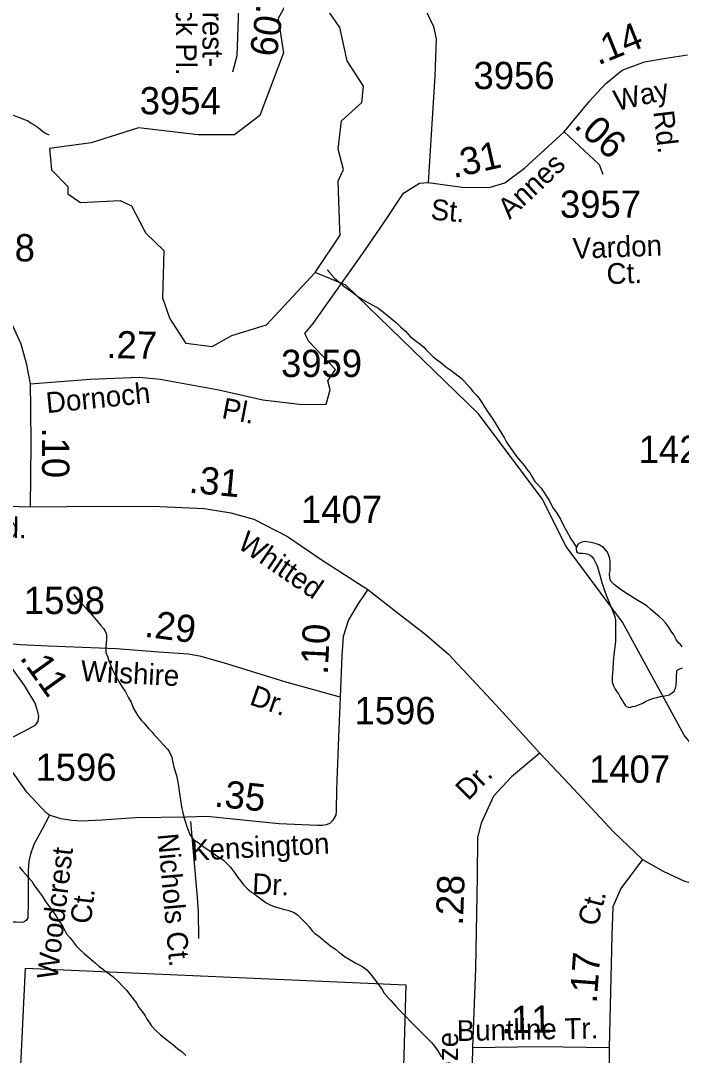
# Model space of a CAD drawing. Extents: x 2001466 to 2224147, y 644118 to 847247.
# Drawn here: x 2068297 to 2071329, y 678756 to 683500 of the extents above; entities that cross this region are included whole.
import ezdxf

# ---------------------------------------------------------------- set-up
doc = ezdxf.new("R2010")
doc.units = 0
for name, color, linetype in [('Exist Boundary Political City Limit New', 7, 'Continuous'), ('Exist Hydrographic Misc Water Feature', 7, 'Continuous'), ('Exist Road Non-System Type 51', 7, 'Continuous'), ('Exist Road Non-System Type 51 Label', 7, 'Continuous'), ('Exist Road Secondary Mileage Hundredths English Label', 7, 'Continuous'), ('Exist Road Secondary Type 51 Attributed', 7, 'Continuous'), ('Exist Road Secondary Type 51 Label', 7, 'Continuous'), ('Exist Road Secondary Type 51 Number Label', 7, 'Continuous'), ('Map Preparation Boundary City Limit Buffer Line', 7, 'Continuous')]:
    doc.layers.add(name, color=color, linetype=linetype)

msp = doc.modelspace()

# ---------------------------------------------------------------- linework, layer by layer
at = {"layer": 'Exist Boundary Political City Limit New'}
msp.add_lwpolyline([(2070065, 679078.5), (2069979.9, 676124.6), (2067235.2, 676200.2), (2067007.2, 676474), (2066845.5, 676712.3), (2066718.2, 677001.4), (2066684.1, 677222.8), (2066689.2, 677418.8), (2066711.6, 677519), (2066797.6, 677765.7), (2066838.9, 678102.1), (2066857.5, 678775), (2068293.8, 678644.4), (2068319.2, 679155.1), (2070065, 679078.5)], dxfattribs=at)
at = {"layer": 'Exist Hydrographic Misc Water Feature'}
for p, q in [((2068863.6, 682539.1), (2068870.7, 682525.4)), ((2069647.7, 682345.6), (2069762.7, 682517.1)), ((2069762.7, 682517.1), (2069761.7, 682540.8))]:
    msp.add_line(p, q, dxfattribs=at)
for points in [[(2069761.7, 682540.8), (2069753.7, 682766.6), (2069778.7, 682818.6), (2069753.7, 682911), (2069769.7, 683041.9), (2069861.8, 683125.4), (2069869.8, 683200.6), (2069794.7, 683317), (2069760.7, 683468.6), (2069677.6, 683591.7), (2069510.7, 683568.8), (2069477.7, 683510.4), (2069502.7, 683352.4)], [(2069502.7, 683352.4), (2069394.6, 683065.9), (2069278.6, 682976.5), (2069111.7, 682976.6), (2068836.7, 683008.4), (2068620.6, 682940.6), (2068428.6, 682915), (2068437.7, 682816.4), (2068512.7, 682739.4), (2068512.7, 682706.6), (2068570.7, 682666.1), (2068753.7, 682675.4), (2068804.7, 682651.5), (2068863.6, 682539.1)], [(2068024.9, 683277.7), (2068042.9, 683240.2), (2068058.7, 683217.9), (2068078.6, 683194.2), (2068096.9, 683176), (2068110.8, 683168.2), (2068149, 683144.2), (2068173.2, 683128.3), (2068195.1, 683112.4), (2068210.9, 683100.3), (2068235.1, 683082.4), (2068257, 683068.6), (2068291.3, 683056.5), (2068317.1, 683046.5), (2068327.1, 683042.5), (2068345, 683030.5), (2068359.1, 683022.7), (2068377.4, 683010.5), (2068385.4, 683002.4), (2068397.5, 682992.6), (2068407.5, 682986.6), (2068419.2, 682980.7), (2068427, 682976.7)], [(2069647.7, 682345.6), (2069423.6, 682104.1), (2069264.6, 682054.8), (2069173.6, 682004.2), (2069056.7, 682019.7), (2068981.7, 682136.1), (2068948.7, 682228.5), (2068955.6, 682444.9), (2068870.7, 682525.4)], [(2069703.7, 682357.7), (2069713.9, 682345.6), (2069737.7, 682319.7), (2069757.6, 682302.1), (2069775.8, 682285.9), (2069810.1, 682262.1), (2069828.1, 682248), (2069843.9, 682236.3), (2069868.1, 682220), (2069889.8, 682208.2), (2069916.1, 682194.1), (2069937.8, 682182.3), (2069962, 682164.4), (2069980.3, 682148.3), (2070019.9, 682116.3), (2070039.9, 682096.6), (2070062.3, 682076.6), (2070084, 682052.6), (2070111.9, 682030.6), (2070128.1, 682018.8), (2070146.4, 682002.6), (2070156.2, 681992.6), (2070190, 681958.7), (2070204.2, 681948.8), (2070224.5, 681932.8), (2070248.3, 681913), (2070266.3, 681900.9), (2070290.5, 681883), (2070318.2, 681861), (2070332.6, 681847.1), (2070354.5, 681821), (2070372.5, 681799.2), (2070394.9, 681777.2), (2070412.7, 681749.3), (2070428.7, 681725.4), (2070442.9, 681703.4), (2070460.7, 681677.1), (2070474.9, 681655.5), (2070492.7, 681625.3), (2070504.8, 681605.6), (2070516.7, 681585.5), (2070526.9, 681567.8), (2070542.9, 681543.4), (2070558.7, 681521.6), (2070572.9, 681501.6), (2070590.9, 681479.8), (2070609.2, 681459.5), (2070618.8, 681445.9), (2070633.2, 681427.5), (2070645.3, 681405.8), (2070657.2, 681387.8), (2070671.1, 681371.9), (2070685, 681356)], [(2072829.5, 678435.8), (2072653.5, 678511.5), (2072570.5, 678618.2), (2072377.5, 679019.1), (2072375, 679070.2), (2072367.6, 679129.4), (2072342, 679180.5), (2072292.9, 679275.5), (2072277.5, 679295.3), (2072268.7, 679305.2), (2072253.3, 679326.9), (2072130.2, 679713.7), (2072075.9, 679756.2), (2071543.6, 679974.4), (2071342.6, 680224.5), (2071058.6, 680742.1), (2070799.7, 681088.6), (2070690.6, 681307.3), (2070398.6, 681697.1), (2069789.6, 682287), (2069647.7, 682345.6)], [(2070685, 681356), (2070723.4, 681297.8), (2070737.3, 681269.8), (2070757.4, 681242), (2070773.6, 681214), (2070787.6, 681185.9), (2070801.7, 681160.3), (2070821.6, 681124), (2070831.7, 681108.2), (2070847.6, 681084.3)], [(2070847.6, 681084.3), (2070845.6, 681080.2), (2070847.6, 681066.1), (2070851.5, 681062.2), (2070859.7, 681058.1), (2070875.5, 681058.2), (2070889.7, 681056.5), (2070901.8, 681054.2), (2070911.8, 681048.3), (2070919.6, 681042.2), (2070927.8, 681030.4), (2070934, 681018.5), (2070939.9, 681006.3), (2070943.8, 680996.3), (2070949.6, 680974.4), (2070955.7, 680952.3), (2070963.7, 680924.3), (2070972.1, 680900.4), (2070983.8, 680866.6), (2070995.9, 680836.7), (2071008.4, 680806.5), (2071014.1, 680790.6), (2071018.5, 680780.6), (2071024.2, 680766.8), (2071026, 680752.7), (2071026.5, 680736.4), (2071026.2, 680720.6), (2071026, 680696.7), (2071026.2, 680674.7), (2071026.2, 680654.5), (2071018.7, 680590.7), (2071016.6, 680560.6), (2071014.8, 680524.4), (2071012.7, 680506.5), (2071010.7, 680488.6), (2071010.7, 680466.6), (2071017, 680450.7), (2071025, 680434.8), (2071032.8, 680422.7), (2071040.8, 680412.6), (2071047, 680400.7), (2071052.9, 680390.9), (2071058.9, 680380.7), (2071065, 680370.8), (2071070.9, 680361), (2071076.7, 680354.8), (2071084.9, 680352.8), (2071093.1, 680350.7), (2071105.2, 680355), (2071119.1, 680356.9), (2071132.9, 680362.9), (2071148.9, 680369.1), (2071164.9, 680378.8), (2071185, 680387.1), (2071202.8, 680392.9), (2071216.7, 680396.9), (2071232.7, 680401), (2071246.7, 680403.3), (2071259, 680405.1), (2071272.7, 680409.1), (2071282.8, 680415.3), (2071288.9, 680419.2), (2071297.1, 680427.3), (2071298.8, 680433.1)], [(2071332.4, 680629.2), (2071324.4, 680639.3), (2071316.2, 680647.1), (2071304.5, 680663), (2071294.2, 680683.3), (2071282.4, 680701.3), (2071270.3, 680720.9), (2071255.9, 680738.9), (2071242, 680754.8), (2071226, 680769), (2071212.2, 680780.8), (2071199.9, 680790.8), (2071188.4, 680800.7), (2071172, 680814.9), (2071160.1, 680822.8), (2071147.8, 680830.7), (2071130, 680840.7), (2071104.2, 680856.8), (2071080.2, 680872.7), (2071053.9, 680888.8), (2071035.9, 680902.5), (2071019.9, 680914.6), (2071005.9, 680930.6), (2071001.8, 680938.4), (2071000, 680948.4), (2070999.8, 680962.3), (2071002.1, 680980.6), (2071001.8, 680994.4), (2071002.1, 681010.6), (2071001.8, 681020.4), (2071000, 681034.5), (2070995.5, 681048.5), (2070989.7, 681062.4), (2070981.5, 681074.5), (2070971.7, 681084.6), (2070951.6, 681096.5), (2070934, 681102.5), (2070915.7, 681108.1), (2070895.8, 681110.3), (2070885.4, 681112.3), (2070871.6, 681108.3), (2070857.9, 681102.2), (2070853.8, 681098.4), (2070849.9, 681090.1), (2070847.6, 681084.3)], [(2068540.6, 680868.2), (2068560.9, 680842), (2068578.7, 680824.3), (2068602.9, 680798.3), (2068624.9, 680774.3), (2068642.7, 680752.1), (2068662.6, 680728.4), (2068676.6, 680712.5), (2068684.8, 680700.3), (2068689.1, 680690.3), (2068691.1, 680682.3), (2068690.7, 680670.2), (2068690.7, 680662.5), (2068688.9, 680646.1), (2068687, 680632.3), (2068686.8, 680618.5), (2068687, 680602.2), (2068695.2, 680584.4), (2068701.2, 680564.4), (2068709.4, 680546.5), (2068717, 680526.3), (2068729.3, 680502.6), (2068751.4, 680462.7), (2068761, 680446.6), (2068777.4, 680422.6), (2068791.4, 680394.5), (2068803.5, 680374.5), (2068813.5, 680348.6), (2068823.4, 680330.5), (2068833.6, 680312.7), (2068841.6, 680302.6), (2068849.8, 680292.8), (2068861.3, 680280.5), (2068883.9, 680254.8), (2068899.4, 680237), (2068909.9, 680224.9), (2068921.8, 680212.9), (2068938, 680194.7), (2068951.9, 680178.8), (2068969.8, 680159), (2068978, 680148.9), (2068989.9, 680123.2), (2068993.6, 680105.1), (2068999.9, 680077), (2069011.8, 680039.1), (2069018, 680008.9), (2069020.2, 679989.2), (2069024.1, 679967.1), (2069026.4, 679946.9), (2069030.3, 679925.2), (2069034.2, 679894.9), (2069042.2, 679861.3), (2069048.3, 679839.3), (2069062.7, 679795.3), (2069074.2, 679765.2), (2069088.7, 679747.2), (2069106.5, 679735.1), (2069132.6, 679715.4), (2069170.3, 679689.4), (2069190.6, 679675.4), (2069206.4, 679663.6), (2069226.5, 679651.6), (2069242.5, 679635.4), (2069258.7, 679619.6), (2069280.4, 679589.6), (2069292.7, 679571.5), (2069306.7, 679553.5), (2069320.8, 679535.6), (2069334.6, 679521.7), (2069356.7, 679503.7), (2069367.2, 679497.7), (2069387.1, 679481.7), (2069410.8, 679463.9), (2069427, 679453.8), (2069444.9, 679444.1), (2069464.8, 679435.9), (2069481.2, 679432.2), (2069500.9, 679425.9), (2069526.7, 679420), (2069551.1, 679410.2), (2069567.1, 679400), (2069576.9, 679390), (2069586.8, 679380.5), (2069606.9, 679360.4), (2069621.2, 679344.4), (2069635.2, 679326.5), (2069647.3, 679314.5), (2069665.3, 679302.4), (2069683, 679286.4), (2069689.3, 679280.5), (2069709.2, 679264.6), (2069720.9, 679256.7), (2069741.6, 679242.6), (2069757.4, 679228.5), (2069771.1, 679218.7), (2069783, 679208.7), (2069819.3, 679186.6), (2069835.5, 679178.9), (2069853.3, 679168.9), (2069867.3, 679160.7)], [(2071298.8, 680433.1), (2071302.9, 680439.4), (2071304.7, 680453.3), (2071306.8, 680475.3), (2071306.8, 680495.2), (2071308.8, 680513.1), (2071308.6, 680519.2), (2071312.5, 680523.1), (2071322.5, 680527.3), (2071334.6, 680533.1)], [(2068289.2, 679619.8), (2068306.6, 679600), (2068329.2, 679573.9), (2068347, 679553.8), (2068357.1, 679538), (2068378.8, 679508), (2068397.1, 679484.1), (2068407.1, 679466), (2068417.4, 679450.2), (2068438.9, 679422.2), (2068459.4, 679394.4), (2068471.5, 679372.3), (2068489.3, 679346.4), (2068499.4, 679328.3), (2068507.4, 679312.1), (2068523.6, 679294.2), (2068541.6, 679270.3), (2068551.5, 679258.3), (2068569.5, 679238.6), (2068587.6, 679222.4), (2068599.7, 679212.5), (2068619.3, 679196.5), (2068639.9, 679178.4), (2068655.8, 679164.6), (2068665.5, 679156.7), (2068691.9, 679136.4), (2068719.6, 679116.9), (2068745.9, 679092.6), (2068763.7, 679072.8), (2068783.8, 679052.8), (2068795.9, 679036.7), (2068817.6, 679008.7), (2068829.9, 678993.1), (2068837.9, 678976.8), (2068854.1, 678956.9), (2068868.1, 678936.9), (2068876.1, 678921.1), (2068886.1, 678907), (2068896.2, 678892.9), (2068915.9, 678871.3), (2068938.2, 678849.3), (2068960.1, 678833.4), (2068974.3, 678821.1), (2068994, 678807.1), (2069018.4, 678785.2), (2069038.3, 678771.2), (2069054.3, 678755.4)], [(2069867.3, 679160.7), (2069885.5, 679147), (2069903.4, 679126.9), (2069919.6, 679106.9), (2069939.5, 679080.8), (2069955.5, 679056.9), (2069965.5, 679041.1), (2069989.7, 679013.2), (2069995.7, 679007), (2070017.6, 678983), (2070035.4, 678963.2), (2070057.8, 678939.2), (2070093.9, 678903.3), (2070106, 678891.3), (2070139.8, 678857.4), (2070151.9, 678845.4), (2070171.8, 678825.3), (2070183.9, 678813.4), (2070196.2, 678797.3), (2070212, 678775.5), (2070228.2, 678747.5)]]:
    msp.add_lwpolyline(points, dxfattribs=at)
at = {"layer": 'Exist Road Non-System Type 51'}
for points in [[(2069698.8, 681741.8), (2069717.8, 681808.2), (2069706.7, 681849.2), (2069741.4, 681901.3), (2069618.4, 682029.2), (2069601, 682065.5), (2069638.9, 682111.3), (2069866.1, 682431.1), (2069963.9, 682573.2), (2070053.1, 682710.2), (2070126.5, 682756), (2070166.7, 682757.6)], [(2069075.3, 679827.7), (2069106.6, 679479.6), (2069111.3, 679414), (2069112.9, 679291.3)]]:
    msp.add_lwpolyline(points, dxfattribs=at)
at = {"layer": 'Exist Road Secondary Type 51 Attributed'}
for points in [[(2069295.3, 683730.5), (2069296.9, 683556), (2069288.2, 683338.5), (2069268.4, 683264.3)], [(2070053.5, 683655.1), (2070145, 683568.2), (2070190.8, 683473.9), (2070204.2, 683417), (2070197.9, 683245.3), (2070185.2, 683051.1), (2070166.7, 682757.6)], [(2070790.8, 682990.1), (2070909.1, 683132.2), (2070981.3, 683211.4), (2071057.8, 683273.7), (2071160.4, 683311.6), (2071257.5, 683328.2), (2071356.5, 683343.8)], [(2070166.7, 682757.6), (2070322.9, 682736.3), (2070447.6, 682735.1), (2070519.4, 682757.2), (2070609.3, 682823.5), (2070790.8, 682990.1)], [(2070790.8, 682990.1), (2070952.5, 682840.9), (2070968.3, 682796.7)], [(2067025.8, 682675.6), (2067145.1, 682631.1), (2067505.1, 682504.7), (2067888.5, 682374.1), (2068062.9, 682297.5), (2068140.2, 682242.2), (2068201.7, 682183.8), (2068258.6, 682103.2), (2068298, 682018), (2068321.7, 681929.9), (2068340.2, 681835)], [(2068340.2, 681835), (2068614.8, 681856.3), (2068842, 681865.8), (2068936.7, 681856.3), (2069206.5, 681807.4), (2069408.5, 681762.4), (2069588.4, 681740.3), (2069698.8, 681741.8)], [(2068340.2, 681835), (2068341.8, 681721.3), (2068343.4, 681557.1), (2068340.2, 681270.5)], [(2066812.8, 681282.8), (2066924.1, 681283.8), (2067271.7, 681279.7), (2067453, 681276.6), (2067836.8, 681285.5), (2068340.2, 681270.5)], [(2068340.2, 681270.5), (2068677.1, 681274), (2068935.9, 681272.5), (2069139.4, 681263), (2069260.9, 681244), (2069366.7, 681214), (2069521.3, 681134.3), (2069680.7, 681026.9), (2069890.6, 680891.9)], [(2069890.6, 680891.9), (2069846.4, 680829.9), (2069800.6, 680752.5), (2069776.9, 680676.8), (2069770.6, 680588.3), (2069762.7, 680397.3)], [(2069890.6, 680891.9), (2070045.2, 680771.1), (2070149.8, 680690.7), (2070259.8, 680595.6), (2070476.8, 680362.9), (2070678.7, 680141.1)], [(2068170.8, 680177.6), (2068267.6, 680219.7), (2068336, 680254.6), (2068366.7, 680271.4), (2068376.5, 680288.1), (2068379.3, 680309), (2068375.1, 680331.4), (2068363.4, 680370.8), (2068313.8, 680452.3), (2068255.9, 680532.6), (2068231.1, 680570.3), (2068218.1, 680602.2), (2068214.6, 680618.7), (2068216.9, 680632.9), (2068228.7, 680641.2), (2068248.7, 680642)], [(2069762.7, 680397.3), (2069508.7, 680469.1), (2069246.7, 680549.6), (2069125.4, 680585.2), (2069066.2, 680595.4), (2068930.7, 680604.8), (2068735.6, 680619.5), (2068423.7, 680631.7), (2068294.9, 680638.8), (2068248.7, 680642)], [(2069762.7, 680397.3), (2069754.8, 680214.9), (2069745.4, 679974.9), (2069744.7, 679877.2), (2069742.6, 679856.3), (2069730, 679834.2), (2069717.4, 679820.6), (2069699.6, 679813.2), (2069679.6, 679810.1), (2069657.6, 679809), (2069482.7, 679816.6), (2069151.3, 679850.5), (2069057.8, 679847.7), (2068823.4, 679844.4), (2068669.3, 679833.4), (2068575.3, 679830), (2068531.7, 679832.6), (2068481.2, 679840.5), (2068428.9, 679856.2)], [(2068428.9, 679856.2), (2068414.8, 679865.7), (2068324.9, 679962), (2068207, 680129.4), (2068170.8, 680177.6)], [(2070678.7, 680141.1), (2070549.3, 680032.5), (2070467.3, 679944.1), (2070410.5, 679820.9), (2070393.1, 679754.6), (2070391.6, 679574.6), (2070383.7, 679155.3), (2070371, 678792.1)], [(2070678.7, 680141.1), (2070813.6, 679998.5), (2071017.2, 679779.8), (2071151.3, 679653.5)], [(2068428.9, 679856.2), (2068394.3, 679789.2), (2068357.4, 679721.9), (2068341.1, 679678.6), (2068333.3, 679643.8), (2068330.7, 679604.4), (2068331.1, 679552.4), (2068330.7, 679447.9), (2068329.4, 679398.3), (2068328.8, 679386.5), (2068324.3, 679377.9), (2068321.9, 679374.3), (2068317, 679370.2), (2068312.5, 679367), (2068304.8, 679365.3), (2068276.5, 679365.9), (2068235.6, 679365.9), (2068122.2, 679372.5)], [(2071151.3, 679653.5), (2071051.1, 679520.9), (2071014.8, 679437.2), (2071010.1, 679303), (2070997.5, 678792.1)], [(2071151.3, 679653.5), (2071246, 679599.8), (2071343.8, 679554), (2071459, 679527.2), (2071537.9, 679504.3), (2071752.5, 679411.1), (2071945, 679316.4), (2072094.9, 679256.4), (2072226.7, 679237)], [(2070371, 678792.1), (2070680.3, 678795.3), (2070997.5, 678792.1)], [(2070371, 678792.1), (2070367.1, 678636.2), (2070367.1, 678361.4), (2070368.7, 678256), (2070342.6, 678153.4), (2070294.5, 678053.1), (2070259.8, 677986.8)], [(2070997.5, 678792.1), (2070998.3, 678483), (2070993.5, 678124.2), (2071004.6, 677824.2)]]:
    msp.add_lwpolyline(points, dxfattribs=at)
at = {"layer": 'Map Preparation Boundary City Limit Buffer Line'}
msp.add_lwpolyline([(2070065, 679078.5), (2069979.9, 676124.6), (2067235.2, 676200.2), (2067007.2, 676474), (2066845.5, 676712.3), (2066718.2, 677001.4), (2066684.1, 677222.8), (2066689.2, 677418.8), (2066711.6, 677519), (2066797.6, 677765.7), (2066838.9, 678102.1), (2066857.5, 678775), (2068293.8, 678644.4), (2068319.2, 679155.1), (2070065, 679078.5)], dxfattribs=at)

# ---------------------------------------------------------------- texts
at = {"layer": 'Exist Road Non-System Type 51 Label'}
for s, rotation, p in [('Nichols Ct.', 275.1369, (2068924.7, 679769.8)), ('Woodcrest', 83.2098, (2068465, 679100.5)), (' Ct.', 83.2098, (2068614, 679319.8))]:
    msp.add_text(s, height=95, rotation=rotation, dxfattribs=at).set_placement(p)
at = {"layer": 'Exist Road Secondary Mileage Hundredths English Label'}
for s, rotation, p in [('.09', 261.7591, (2069380.6, 683579)), ('.14', 21.9775, (2070947, 683294.8)), ('.06', 318.2796, (2070831.4, 683013.5)), ('.31', 12.8699, (2070283.5, 682777.7)), ('.27', 358.837, (2068689.1, 681953.4)), ('.10', 270.3288, (2068393.7, 681634.7)), ('.31', 354.677, (2069066, 681336.2)), ('.29', 352.5177, (2068861.3, 680675.9)), ('.10', 87.1737, (2069705.6, 680499.7)), ('.11', 305.719, (2068289.2, 680578.5)), ('.35', 354.1504, (2069182.2, 679896.8)), ('.28', 87.9555, (2070326.3, 679349.2)), ('.17', 85.603, (2070939.8, 678991.4)), ('.11', 1.0813, (2070502.4, 678855.9))]:
    msp.add_text(s, height=125, rotation=rotation, dxfattribs=at).set_placement(p)
at = {"layer": 'Exist Road Secondary Type 51 Label'}
for s, rotation, p in [('wick Pl.', 270, (2069009.2, 683678.9)), ('Prest-', 270, (2069131.2, 683626.5)), ('Way', 13.0002, (2071031.5, 683085.6)), ('Rd.', 276.662, (2071200.1, 683083.9)), ('Annes', 43.1919, (2070541.1, 682586.4)), ('St.', 354.931, (2070175.7, 682588.8)), ('Vardon', 2.1401, (2070832.2, 682408.2)), (' Ct.', 2.1401, (2070952, 682290.6)), ('Dornoch', 5.713, (2068417.4, 681700.4)), ('Pl.', 349.1177, (2069215.5, 681678.9)), ('Rd.', 358.8374, (2068126, 681130.9)), ('Whitted', 325.6381, (2069286.5, 681086.6)), ('Wilshire', 356.9841, (2068570.8, 680472.1)), ('Dr.', 340.7527, (2069342, 680366.1)), ('Dr.', 44.9703, (2070349.9, 679919.8)), ('Kensington', 3.0566, (2069081.1, 679647.7)), ('Dr.', 357.329, (2069357.5, 679495.8)), ('Ct.', 75.0746, (2070943.4, 679342.6)), ('Buntline Tr.', 1.0813, (2070298.9, 678821)), ('Stillbreeze', 89.2841, (2070297.2, 678269.3))]:
    msp.add_text(s, height=95, rotation=rotation, dxfattribs=at).set_placement(p)
at = {"layer": 'Exist Road Secondary Type 51 Number Label'}
for s, p in [('3956', (2070375.1, 683186.7)), ('3954', (2068843, 683071)), ('3957', (2070772, 682596.6)), ('3958', (2067990.1, 682396.5)), ('3959', (2069491.6, 681866.3)), ('1421', (2071133.3, 681472.5)), ('1407', (2069583.3, 681196.5)), ('1598', (2068311.3, 680779.3)), ('1596', (2069829, 680274.1)), ('1596', (2068364.6, 680014.4)), ('1407', (2070905.4, 680005.6))]:
    msp.add_text(s, height=125, dxfattribs=at).set_placement(p)

doc.saveas('drawing.dxf')
